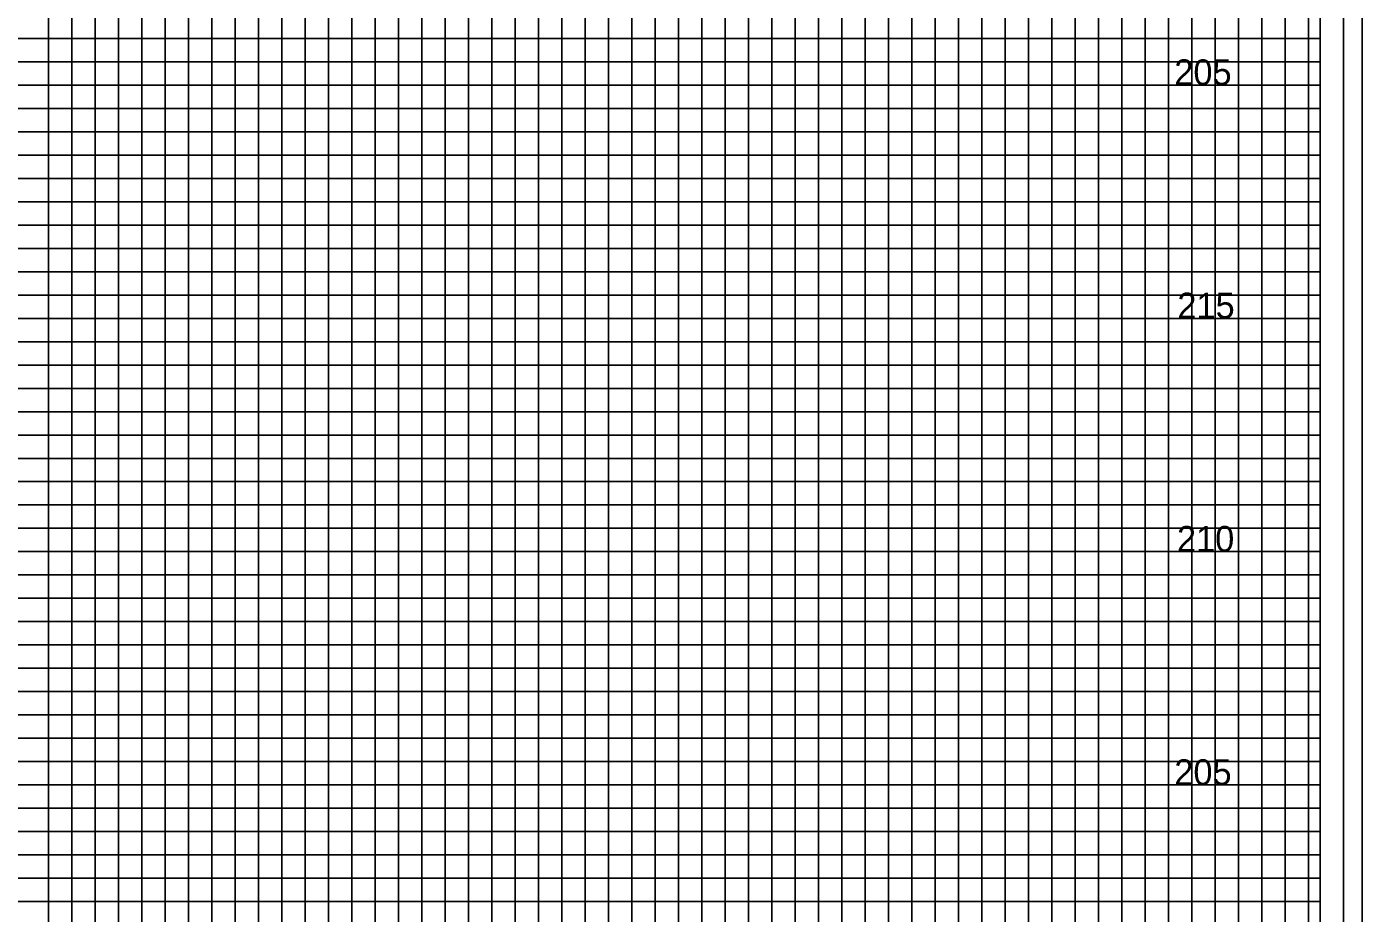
# Model space of a CAD drawing. Extents: x -4 to 103, y -2 to 67.
# Drawn here: x 74.78 to 103.4, y 32.25 to 51.25 of the extents above; entities that cross this region are included whole.
import ezdxf

# ---------------------------------------------------------------- set-up
doc = ezdxf.new("R2010")
doc.units = 0
for name, color, linetype in [('Old_Level_10', 7, 'Continuous'), ('Old_Level_5', 7, 'Continuous'), ('Old_Level_8', 7, 'Continuous'), ('Prop XS Dump Level', 7, 'Continuous'), ('Prop XS EOT Tick Mark', 7, 'Continuous'), ('Prop XS Subgrade Concrete', 7, 'Continuous'), ('Typical Curb CELL', 7, 'Continuous')]:
    doc.layers.add(name, color=color, linetype=linetype)

msp = doc.modelspace()

# ---------------------------------------------------------------- linework, layer by layer
at = {"layer": 'Old_Level_10'}
for p, q in [((91.25, 0), (91.25, 63.425)), ((93.75, 0), (93.75, 63.425)), ((96.25, 0), (96.25, 63.425)), ((98.75, 0), (98.75, 63.425)), ((101.25, 0), (101.25, 63.425)), ((76.25, 0), (76.25, 62)), ((78.75, 0), (78.75, 62)), ((81.25, 0), (81.25, 62)), ((83.75, 0), (83.75, 62)), ((86.25, 0), (86.25, 62)), ((88.75, 0), (88.75, 62)), ((0, 50), (102.5, 50)), ((0, 47.5), (102.5, 47.5)), ((0, 45), (102.5, 45)), ((0, 42.5), (102.5, 42.5)), ((0, 40), (102.5, 40)), ((0, 37.5), (102.5, 37.5)), ((0, 35), (102.5, 35)), ((0, 32.5), (102.5, 32.5))]:
    msp.add_line(p, q, dxfattribs=at)
at = {"layer": 'Old_Level_5'}
msp.add_lwpolyline([(103.4, 67.4), (-3.5, 67.4), (-3.5, -2.425), (103.4, -2.425)], close=True, dxfattribs=at)
at = {"layer": 'Old_Level_8'}
for points in [[(91.25, 0), (91.25, 63.425), (93.75, 63.425), (93.75, 0)], [(96.25, 0), (96.25, 63.425), (98.75, 63.425), (98.75, 0)], [(101.25, 0), (101.25, 63.425)], [(76.25, 0), (76.25, 62), (78.75, 62), (78.75, 0)], [(81.25, 0), (81.25, 62), (83.75, 62), (83.75, 0)], [(86.25, 0), (86.25, 62), (88.75, 62), (88.75, 0)], [(0, 47.5), (102.5, 47.5), (102.5, 50), (0, 50)], [(0, 42.5), (102.5, 42.5), (102.5, 45), (0, 45)], [(0, 37.5), (102.5, 37.5), (102.5, 40), (0, 40)], [(0, 32.5), (102.5, 32.5), (102.5, 35), (0, 35)]]:
    msp.add_lwpolyline(points, dxfattribs=at)
at = {"layer": 'Prop XS Dump Level'}
for points in [[(90.25, 0), (90.25, 63.425), (90.75, 63.425), (90.75, 0)], [(91.75, 0), (91.75, 63.425), (92.25, 63.425), (92.25, 0)], [(92.75, 0), (92.75, 63.425), (93.25, 63.425), (93.25, 0)], [(94.25, 0), (94.25, 63.425), (94.75, 63.425), (94.75, 0)], [(95.25, 0), (95.25, 63.425), (95.75, 63.425), (95.75, 0)], [(96.75, 0), (96.75, 63.425), (97.25, 63.425), (97.25, 0)], [(97.75, 0), (97.75, 63.425), (98.25, 63.425), (98.25, 0)], [(99.25, 0), (99.25, 63.425), (99.75, 63.425), (99.75, 0)], [(100.25, 0), (100.25, 63.425)], [(100.25, 63.425), (100.75, 63.425), (100.75, 0), (101.75, 0), (101.75, 63.425), (102.25, 63.425), (102.25, 0)], [(75.25, 0), (75.25, 62), (75.75, 62), (75.75, 0)], [(76.75, 0), (76.75, 62), (77.25, 62), (77.25, 0)], [(77.75, 0), (77.75, 62), (78.25, 62), (78.25, 0)], [(79.25, 0), (79.25, 62), (79.75, 62), (79.75, 0)], [(80.25, 0), (80.25, 62), (80.75, 62), (80.75, 0)], [(81.75, 0), (81.75, 62), (82.25, 62), (82.25, 0)], [(82.75, 0), (82.75, 62), (83.25, 62), (83.25, 0)], [(84.25, 0), (84.25, 62), (84.75, 62), (84.75, 0)], [(85.25, 0), (85.25, 62), (85.75, 62), (85.75, 0)], [(86.75, 0), (86.75, 62), (87.25, 62), (87.25, 0)], [(87.75, 0), (87.75, 62), (88.25, 62), (88.25, 0)], [(89.25, 0), (89.25, 62), (89.75, 62), (89.75, 0)], [(0, 50.5), (102.5, 50.5), (102.5, 51), (0, 51)], [(0, 49), (102.5, 49), (102.5, 49.5), (0, 49.5)], [(0, 48), (102.5, 48), (102.5, 48.5), (0, 48.5)], [(0, 46.5), (102.5, 46.5), (102.5, 47), (0, 47)], [(0, 45.5), (102.5, 45.5), (102.5, 46), (0, 46)], [(0, 44), (102.5, 44), (102.5, 44.5), (0, 44.5)], [(0, 43), (102.5, 43), (102.5, 43.5), (0, 43.5)], [(0, 41.5), (102.5, 41.5), (102.5, 42), (0, 42)], [(0, 40.5), (102.5, 40.5), (102.5, 41), (0, 41)], [(0, 39), (102.5, 39), (102.5, 39.5), (0, 39.5)], [(0, 38), (102.5, 38), (102.5, 38.5), (0, 38.5)], [(0, 36.5), (102.5, 36.5), (102.5, 37), (0, 37)], [(0, 35.5), (102.5, 35.5), (102.5, 36), (0, 36)], [(0, 34), (102.5, 34), (102.5, 34.5), (0, 34.5)], [(0, 33), (102.5, 33), (102.5, 33.5), (0, 33.5)]]:
    msp.add_lwpolyline(points, dxfattribs=at)
at = {"layer": 'Prop XS Subgrade Concrete'}
msp.add_lwpolyline([(102.5, 65), (0, 65), (0, 0), (102.5, 0)], close=True, dxfattribs=at)
at = {"layer": 'Typical Curb CELL'}
msp.add_lwpolyline([(103, 66), (-2.8, 66), (-2.8, -1), (103, -1)], close=True, dxfattribs=at)

# ---------------------------------------------------------------- texts
at = {"layer": 'Prop XS EOT Tick Mark'}
for s, p in [('205', (99.3724, 50)), ('215', (99.4383, 45)), ('210', (99.4296, 40)), ('205', (99.3724, 35))]:
    msp.add_text(s, height=0.55, dxfattribs=at).set_placement(p)

doc.saveas('drawing.dxf')
